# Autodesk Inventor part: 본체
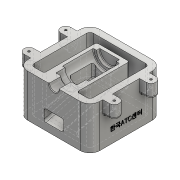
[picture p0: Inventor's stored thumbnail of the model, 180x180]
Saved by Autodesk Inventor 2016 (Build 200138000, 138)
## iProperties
Created: 2018-01
Part Number: 본체
Material: 알루미늄 6061
Document SubType Name: Modeling
Designer: Administrator
Density: 2.7 g/cm^3
Appearance: 알루미늄 - 평지
Mass: 995.067 g
Surface Area: 839.2 cm^2
Volume: 368.543 cm^3
Author: Administrator
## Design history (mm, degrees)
sketch "스케치1"
  geometry: L1 (-55, -55)-(55, -55); L2 (55, -55)-(55, 55); L3 (55, 55)-(-55, 55); L4 (-55, 55)-(-55, -55); L5 (-55, -55)-(55, 55); L6 (55, -55)-(-55, 55); 1 further point
  constraints: 12 end point, 2 midpoint, 2 parallel, 1 horizontal, 1 perpendicular
  dimensions: "d0" = 110 distance of L3.end L2.end; "d1" = 110 distance of L2.end L1.end
extrude "돌출1" new body sketch "스케치1" distance "d2" = 65; taper "d3" = 0 deg
sketch "스케치7"
  geometry: L1 (-55, -55)-(55, -55) reference; L2 (55, -55)-(55, 55) reference; L3 (55, 55)-(-55, 55) reference; L4 (-55, 55)-(-55, -55) reference; L5 (-45, 45)-(45, 45); L6 (45, 45)-(45, -45); L7 (45, -45)-(-45, -45); L8 (-45, -45)-(-45, 45); 1 further point
  constraints: 8 end point, 3 other
  dimensions: "d45" = 10 distance between parallel lines of L3 L5
extrude "돌출3" cut sketch "스케치7" stored distance "d46" = 30; taper "d47" = 0 deg
sketch "스케치8"
  geometry: L1 (45, -45)-(-45, -45) reference; L2 (55, 55)-(-55, 55) reference; L3 (-25, 35)-(25, 35); L4 (25, 35)-(25, -45); L5 (25, -45)-(-25, -45); L6 (-25, -45)-(-25, 35); 2 further points
  constraints: 8 end point, 2 midpoint, 2 parallel, 1 horizontal, 1 perpendicular
  dimensions: "d48" = 20 distance between parallel lines of L2 L3; "d49" = 50 distance between parallel lines of L6 L4
extrude "돌출4" join sketch "스케치8" distance "d50" = 40; taper "d51" = 0 deg
sketch "스케치9"
  geometry: L1 (45, 65)-(-45, 65) reference; L2 (30, 65)-(30, 50); L3 (30, 50)-(25, 50); L4 (25, 50)-(25, 45); L5 (25, 45)-(-22, 45); L6 (-22, 45)-(-22, 49); L7 (-22, 49)-(-36, 49); L8 (-36, 49)-(-36, 57.5); L9 (-36, 57.5)-(-55, 57.5); L10 (-55, 0)-(-55, 65) reference; L11 (-55, 57.5)-(-55, 65); L12 (55, 65)-(-55, 65) reference; L13 (30, 65)-(-55, 65); L14 (55, 65)-(-76.041, 65); 1 further point
  constraints: 22 end point, 8 perpendicular, 2 horizontal, 2 point on line, 1 collinear
  dimensions: "d52" = 30 diameter of L2.end L14; "d53" = 40 diameter of L5 L14; "d54" = 32 diameter of L7 L14; "d55" = 15 diameter of L9.end L14; "d56" = 47 distance of L4.end L5.end; "d57" = 5 distance of L2.end L3.end; "d58" = 19 distance of L8.end L9.end; "d59" = 14 distance of L6.end L7.end
revolve "회전3" sketch "스케치9" stored, may be unused: angle "d60" = 90 deg
sketch "스케치11"
  geometry: L1 (-55, 55)-(-55, -55) reference; L2 (-55, -55)-(-7.5, -55) reference; L3 (-55, -20.5)-(-65, -20.5); L4 (-65, -35.5)-(-55, -35.5); L5 (-55, -35.5)-(-55, -20.5); A1 r 7.5 centre (-65, -28) between (-65, -20.5) and (-65, -35.5); 1 further point
  constraints: 6 end point, 2 point on circle, 1 centre point, 1 horizontal, 1 parallel, 1 point on line
  dimensions: "d71" = 10 distance of L3.start L3.end; "d72" = 7.5 radius of A1; "d73" = 27 distance from line of A1.centre L2; "d74" = 10 distance from line of L1 A1.centre
extrude "돌출6" join sketch "스케치11" distance "d75" = 20; taper "d76" = 0 deg
sketch "스케치15"
  geometry: L1 (20, 31.157)-(-55, 11.061); L2 (-55, 11.061)-(-55, 29.061); L3 (-55, 29.061)-(-17, 39.243); L4 (-17, 39.243)-(-17, 45); L5 (20, 31.157)-(20, 45); 3 further points
  constraints: 10 end point, 1 parallel
  dimensions: "d93" = 18 distance of L1.end L2.end
extrude "돌출8" cut sketch "스케치15" stored distance "d99" = 30; taper "d100" = 0 deg
hole "구멍1" diameter "d103" = 3.242; stored, may be unused: countersink angle "d107" = 90 deg, drill point angle "d109" = 118 deg; dims "d101" = 10, "d102" = 10, "d104" = 9, "d105" = 4, "d106" = 2, "d108" = 11
fillet "모깎기1" dims "d116" = 5, "d117" = 3
fillet "모깎기2" dims "d118" = 1
chamfer "모따기1" distance "d119" = 1; stored, may be unused: second distance "d120" = 2, angle "d121" = 45 deg
fillet "모깎기3" dims "d122" = 3
sketch "스케치17"
  geometry: L1 (-40, 65)-(40, 65) reference; L2 (35, 65)-(35, 30); L3 (35, 30)-(-45, 8.564); L4 (-45, 8.564)-(-45, 0); L5 (40, 0)-(-40, 0) reference; L6 (40, 0)-(45, 0) reference; L7 (-55, 0)-(-55, 65) reference; L8 (55, 0)-(55, 65) reference; L9 (35, 65)-(45, 65); L10 (55, 65)-(35.5, 65) reference; L11 (45, 65)-(45, 0); L12 (55, 0)-(-55, 0) reference; L13 (-45, 0)-(45, 0); 1 further point
  constraints: 12 end point, 4 point on line, 1 collinear, 1 parallel, 1 perpendicular, 1 vertical
  dimensions: "d123" = 30 distance from line of L6 L2.end; "d124" = 105 deg angle of L4 L3; "d125" = 10 distance between parallel lines of L7 L4; "d126" = 20 distance between parallel lines of L8 L2; "d127" = 10 distance of L2.start L9.end
extrude "돌출9" cut sketch "스케치17" stored distance "d128" = 50; taper "d129" = 0 deg
sketch "스케치19"
  geometry: L1 (-45, 13.74)-(-55, 11.061) reference; L2 (-55, 11.061)-(-45, 13.74); L3 (17, 30.353)-(-2.979, 25) reference; L4 (-2.979, 25)-(20.269, 31.229); L5 (20.269, 31.229)-(35, 31.229); L6 (35, 65)-(35, 30) reference; L7 (35, 30)-(35, 31.229); L8 (35, 30)-(-45, 8.564); L9 (-45, 8.564)-(-55, 5.885); L10 (-55, 5.885)-(-55, 11.061); L11 (-55, 0)-(-55, 65) reference; L12 (-45, 13.74)-(-2.979, 25); 2 further points
  constraints: 16 end point, 4 collinear, 2 point on line, 1 parallel
extrude "돌출11" join sketch "스케치19" stored distance "d132" = 50; taper "d133" = 0 deg
fillet "모깎기5" dims "d135" = 3
sketch "스케치20"
  geometry: L1 (-40, 0)-(-40, 39.021) reference; L2 (-40, 39.021)-(-51.26, -3) reference; L3 (-40, 39.021)-(-40, -3); L4 (-51.26, -3)-(-53.939, -13) reference; L5 (-40, -3)-(-51.26, -3); 1 further point
  constraints: 4 end point, 1 perpendicular, 1 point on line
extrude "돌출12" join sketch "스케치20" distance "d136" = 10; taper "d137" = 0 deg
sketch "스케치21"
  geometry: L1 (40, 39.021)-(40, 0) reference; L2 (40, 39.021)-(51.26, -3) reference; L3 (51.26, -3)-(40, -3); L4 (40, -3)-(40, 39.021) reference; L5 (40, -3)-(40, 39.021); L6 (40, 39.021)-(51.26, -3); L7 (40, -3)-(51.26, -3); L8 (40, -3)-(51.26, -3); L9 (40, -3)-(51.26, -3); 1 further point
  constraints: 12 end point, 4 collinear
extrude "돌출13" join sketch "스케치21" distance "d138" = 10; taper "d139" = 0 deg
fillet "모깎기6" dims "d140" = 3
fillet "모깎기7" dims "d141" = 3
fillet "모깎기8" dims "d142" = 15
fillet "모깎기9" dims "d143" = 3
fillet "모깎기10" dims "d144" = 3
fillet "모깎기11" dims "d145" = 3
sketch "스케치22"
  geometry: L1 (45, -60.5)-(45, 19.5) reference; L2 (-20, -75.5)-(45, -75.5) reference; 2 further points
  constraints: 1 other
  dimensions: "d146" = 20 distance from line of L1 point (25, -20.5); "d147" = 55 distance from line of L2 point (25, -20.5)
feature "엠보싱1" sketch "스케치22" dims "d148" = 0.5, "d149" = 0
fillet "모깎기12" dims "d150" = 3
node "솔리드1"
mirror "대칭2"
mirror "대칭3"
mirror "대칭4"
pattern_linear "직사각형 패턴1" dims "d112" = 56
pattern_linear "직사각형 패턴2"
